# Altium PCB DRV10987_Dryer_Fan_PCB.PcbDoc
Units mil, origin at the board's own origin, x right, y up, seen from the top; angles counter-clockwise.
Board outline 2502.18 x 2296.58 mil, 2 copper layers (Top Layer, Bottom Layer), stack 65.2 mil thick; 22 components, 16 nets, 63 pads, 534 vias.
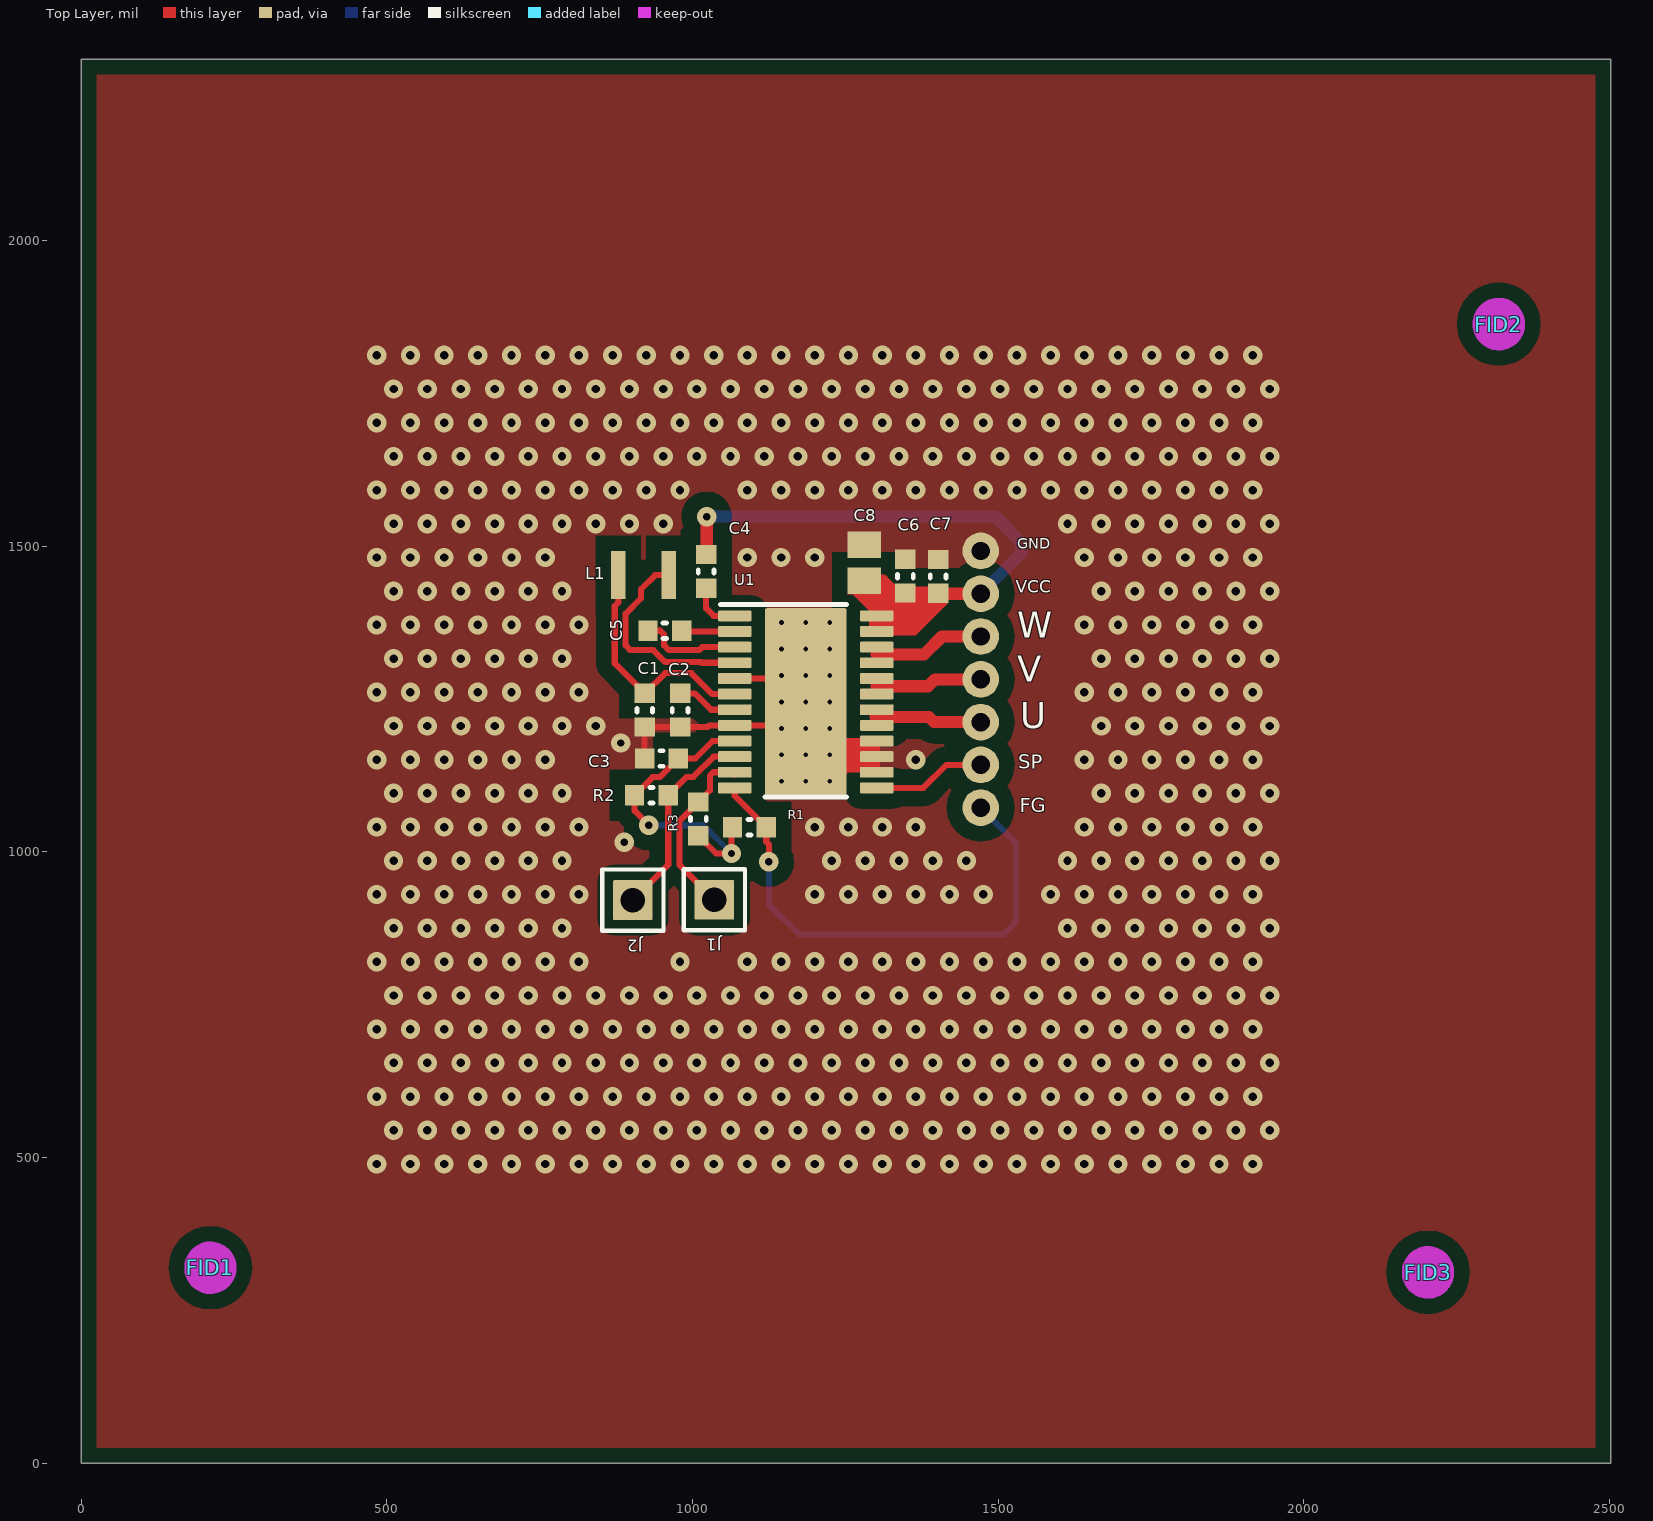
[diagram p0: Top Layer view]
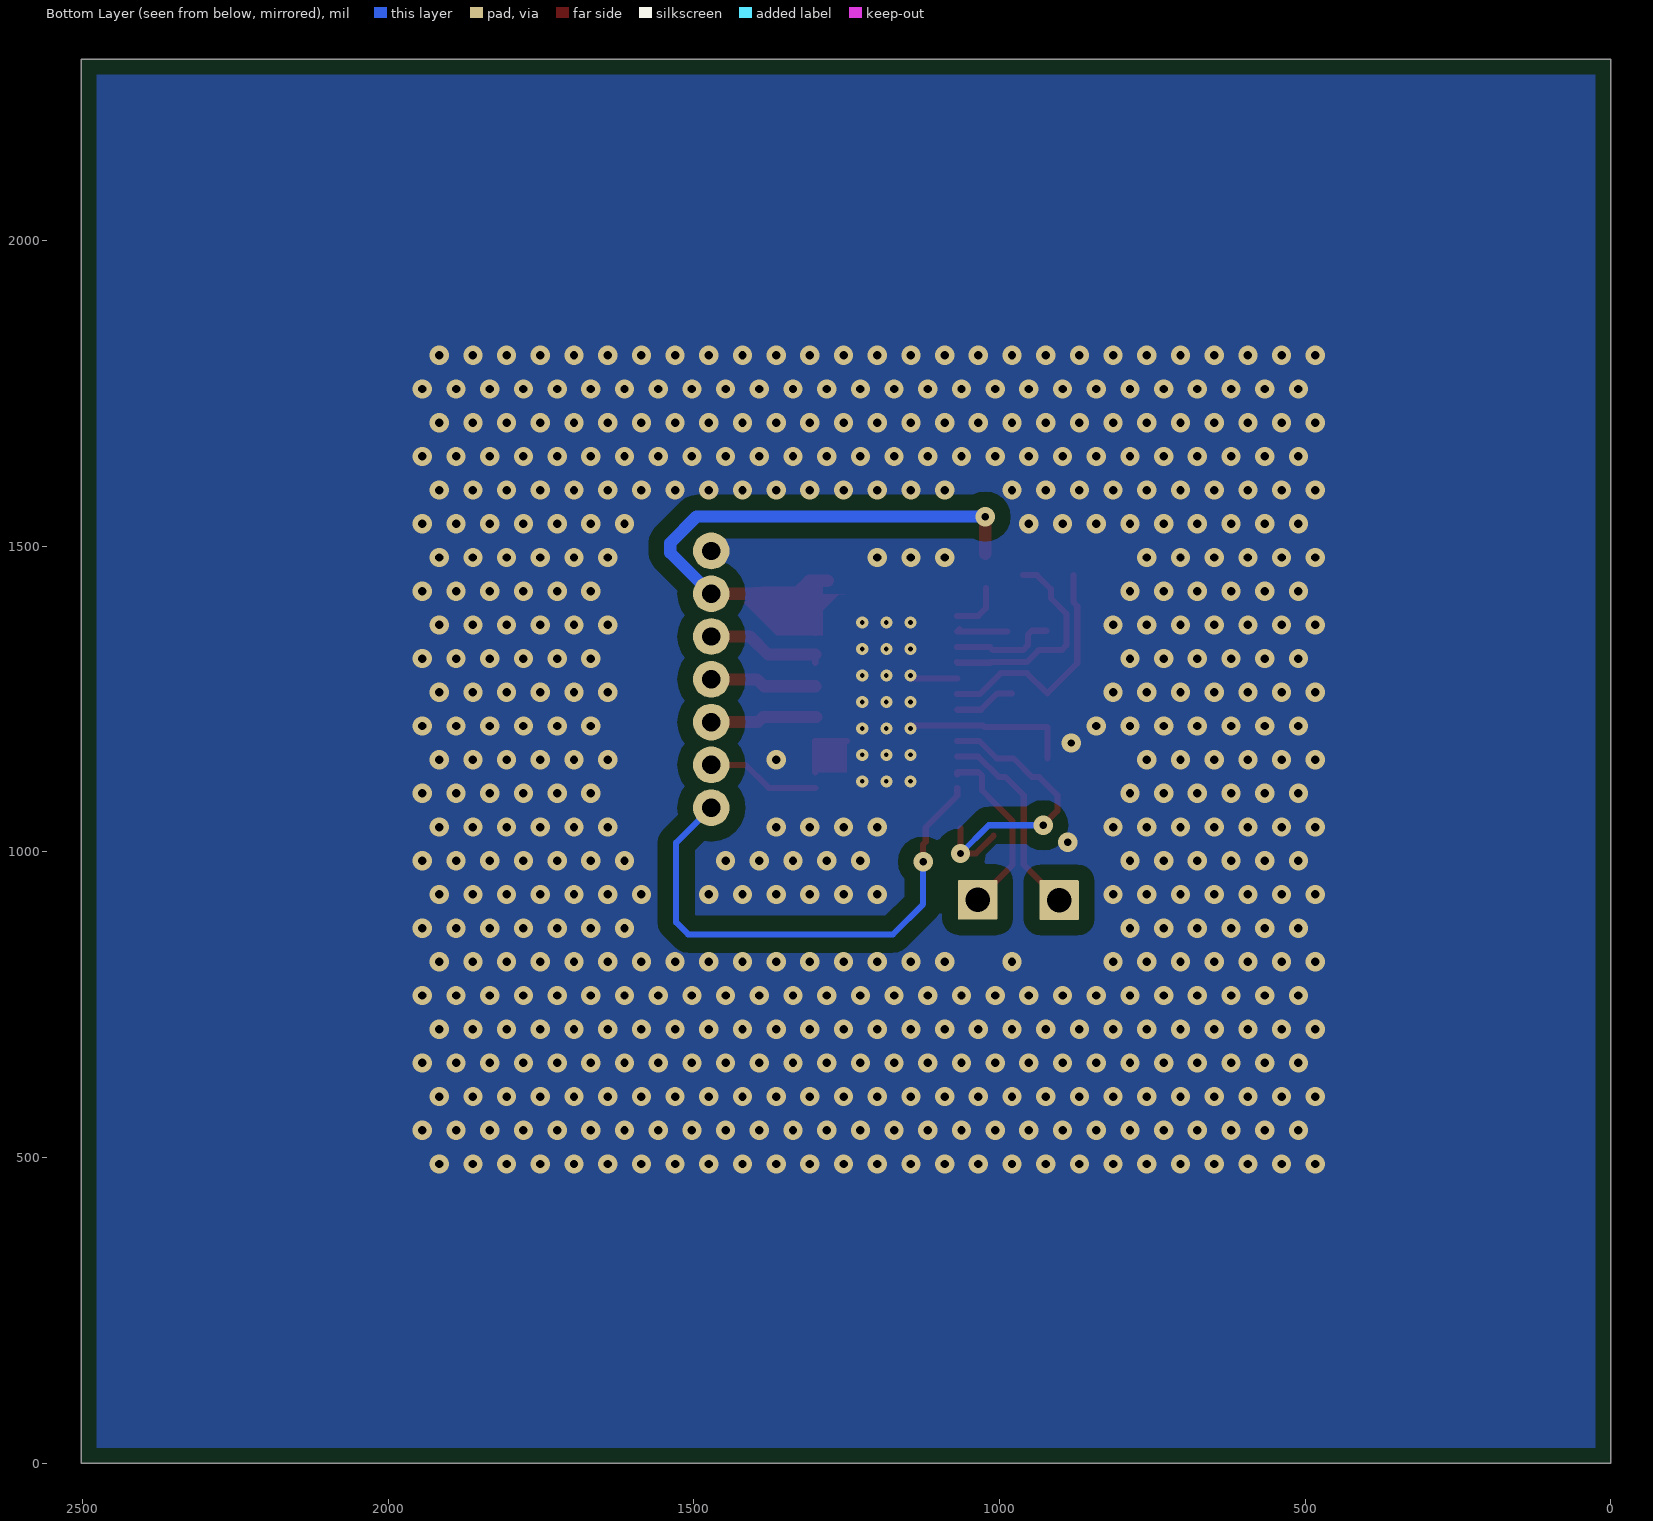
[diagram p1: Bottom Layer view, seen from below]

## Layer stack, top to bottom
Top Solder: solder mask 0.4, Solder Resist, Dk 3.5
Top Layer: signal copper 3
Dielectric1: core 59.2, FR-4, Dk 4.8
Bottom Layer: signal copper 3
Bottom Solder: solder mask 0.4, Solder Resist, Dk 3.5

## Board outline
0,0 0,2296.58 2502.18,2296.58 2502.18,0

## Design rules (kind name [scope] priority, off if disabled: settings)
AcuteAngle [All] p1: minimum=4.50000000000000E+0001 checktracksonly=FALSE
AssemblyTestPointUsage [All] p1: valid=2
BoardOutlineClearance BoardOutlineClearance_MountingHoles [OnCopper and InComponentClass('Mounting Holes')] p1: gap=40 ignorepadtopadclearanceinfootprint=FALSE
BoardOutlineClearance BoardOutlineClearance_Poly [OnCopper and IsPoly] p2: gap=25 ignorepadtopadclearanceinfootprint=FALSE
BoardOutlineClearance [OnCopper and Not InComponentClass('Logo') and not InComponentClass('FiducialMark') and not InRegion(1000,500,4000,800) and not InPoly] p3: gap=75 ignorepadtopadclearanceinfootprint=FALSE
Clearance "Stitching GND" [IsStitchingVia and InNet('GND') vs (IsVia and (Not IsStitchingVia)) Or IsPad] p1: gap=5 ignorepadtopadclearanceinfootprint=FALSE except(0: Arc-Hole Track-Hole SMDPad-Hole THPad-Hole Via-Hole Fill-Hole Poly-Hole Region-Hole Text-Hole)
Clearance Clearance_Keepouts [((IsTrack Or IsArc) And Not InPoly) And IsFree and IsKeepOut vs ((IsTrack Or IsArc) And Not InPoly) And IsFree and IsKeepOut] p2: gap=0 ignorepadtopadclearanceinfootprint=FALSE
Clearance Clearance_FiducialMark [IsKeepOut and InComponentClass('FiducialMark') vs IsPad and InComponentClass('FiducialMark')] p3: gap=0 ignorepadtopadclearanceinfootprint=FALSE
Clearance Clearance_Poly [InPolygon] p4: gap=25 ignorepadtopadclearanceinfootprint=FALSE except(0: Arc-Hole Track-Hole SMDPad-Hole THPad-Hole Via-Hole Fill-Hole Poly-Hole Region-Hole Text-Hole)
Clearance [All] p5: gap=7.87 ignorepadtopadclearanceinfootprint=FALSE except(0: Arc-Hole Track-Hole SMDPad-Hole THPad-Hole Via-Hole Fill-Hole Poly-Hole Region-Hole Text-Hole)
ComponentClearance ComponentClearance_MountingHoles_FiducialMarks [InComponentClass('Mounting Holes') vs InComponentClass('FiducialMark')] p1: gap=50 collisioncheckmode=3 verticalgap=10 showdistances=FALSE
ComponentClearance ComponentClearance_Shunt [InComponentClass('Header') vs InComponentClass('Shunt')] p2: gap=0 collisioncheckmode=3 verticalgap=0 showdistances=FALSE
ComponentClearance ComponentClearance_Logo [InComponentClass('Logo')] p3: gap=50 collisioncheckmode=3 verticalgap=10 showdistances=FALSE
ComponentClearance ComponentClearance_ScrewToNut [(HasFootprint('NY PMS 440 0025 PH')) vs (HasFootprint('Keystone_1902C'))] p4: gap=5 collisioncheckmode=3 verticalgap=10 showdistances=FALSE
ComponentClearance ComponentClearance_MountingHoles [InComponentClass('Mounting Holes')] p5: gap=250 collisioncheckmode=3 verticalgap=100000 showdistances=FALSE
ComponentClearance ComponentClearance_SmallPassives [HasFootprint('0201*') or HasFootprint('0402*') or HasFootprint('0508') or HasFootprint('0603*') or HasFootprint('0612') or HasFootprint('0805*') or HasFootprint('0815*') or HasFootprint('0830*') or HasFootprint('1206*') or HasFootprint('1210*') or HasFootprint('1808*') or HasFootprint('1812*') or HasFootprint('1825*') or HasFootprint('2010*') or HasFootprint('2220*') or HasFootprint('2225*') or HasFootprint('2512*') or HasFootprint('2728*') or HasFootprint('3518*') vs HasFootprint('0201*') or HasFootprint('0402*') or HasFootprint('0508') or HasFootprint('0603*') or HasFootprint('0612') or HasFootprint('0805*') or HasFootprint('0815*') or HasFootprint('0830*') or HasFootprint('1206*') or HasFootprint('1210*') or HasFootprint('1808*') or HasFootprint('1812*') or HasFootprint('1825*') or HasFootprint('2010*') or HasFootprint('2220*') or HasFootprint('2225*') or HasFootprint('2512*') or HasFootprint('2728*') or HasFootprint('3518*')] p6: gap=14.96 collisioncheckmode=3 verticalgap=10 showdistances=FALSE
ComponentClearance ComponentClearance_THtoSMT [IsThruComponent vs IsSMTComponent] p7: gap=40 collisioncheckmode=3 verticalgap=30 showdistances=FALSE
ComponentClearance ComponentClearance_THtoTH [IsThruComponent vs IsThruComponent] p8: gap=30 collisioncheckmode=3 verticalgap=30 showdistances=FALSE
ComponentClearance [All] p9: gap=30 collisioncheckmode=3 verticalgap=10 showdistances=FALSE
DiffPairsRouting [All] p1: maxlimit=100 minlimit=10 mostfreqgap=10 toplayer_minwidth=15 toplayer_maxwidth=15 toplayer_prefwidth=15 bottomlayer_minwidth=15 bottomlayer_maxwidth=15 bottomlayer_prefwidth=15 maxuncoupledlength=1000
FabricationTestPointUsage TestPointUsage [All] p1: valid=2 allowmultiple=FALSE
FabricationTestpoint Testpoint [All] p1: side=3 testpointundercomponent=TRUE minsize=40 maxsize=100 preferedsize=60 minholesize=0 maxholesize=40 preferedholesize=32 testpointgrid=1 allowsidetop=TRUE allowsidebottom=TRUE usegrid=TRUE gridtolerance=0.01
FanoutControl Fanout_LCC [IsLCC] p1: bgadir=Out bgaviamode=Centered fanoutstyle=Auto fanoutdirection=Alternating viagrid=1 // Fanout_LCC (Default Rule)
FanoutControl Fanout_BGA [IsBGA] p2: bgadir=Out bgaviamode=Centered fanoutstyle=Auto fanoutdirection=Alternating viagrid=1 // Fanout_BGA (Default Rule)
FanoutControl Fanout_Default [All] p4: bgadir=Out bgaviamode=Centered fanoutstyle=Auto fanoutdirection=Alternating viagrid=1 // Fanout_Default (Default Rule)
FanoutControl Fanout_Small [(CompPinCount < 5)] p5: bgadir=Out bgaviamode=Centered fanoutstyle=Auto fanoutdirection=OutThenIn viagrid=1 // Fanout_Small (Default Rule)
HoleSize [All] p1: absolutevalues=TRUE maxlimit=251 minlimit=7.87 maxpercent=80.000 minpercent=20.000
MinimumAnnularRing MinimumAnnularRing_ThermalPadVias [IsVia and InAnyComponent] p1: minimumring=5.91
MinimumAnnularRing [All] p2: minimumring=8
MinimumSolderMaskSliver MinimumSolderMaskSliver_Logo [InComponentClass('Logo') vs InComponentClass('Logo')] p1: minsoldermaskwidth=0.7
MinimumSolderMaskSliver [All] p2: minsoldermaskwidth=3.94
PlaneConnect [All] p1: planeconnectstyle=Relief reliefexpansion=10 reliefentries=4 reliefconductorwidth=10 reliefairgap=10
PolygonConnect PolygonConnect_1 [All vs IsNamedPolygon('Top Layer-No Net')] p1: connectstyle=Direct reliefconductorwidth=10 reliefentries=4 polygonreliefangle="90 Angle" airgapwidth=10
PolygonConnect [All] p2: connectstyle=Relief reliefconductorwidth=10 reliefentries=4 polygonreliefangle="90 Angle" airgapwidth=10
RoutingVias ThermalPadVias [IsVia and InAnyComponent] p1: holewidth=7.87 width=19.68 viastyle="Through Hole" minholewidth=7.87 minwidth=19.68 maxholewidth=12.99 maxwidth=23.62
RoutingVias [All] p2: holewidth=16 width=34 viastyle="Through Hole" minholewidth=7.87 minwidth=26 maxholewidth=40 maxwidth=65
SilkToBoardRegionClearance [Not ((IsComment or IsDesignator) And (Hide <> 'False')) and not InRegion(1000,500,4000,800)] p1:
SilkToSilkClearance SilkToSilkClearance_Pb-FreeLogo [(HasFootprint('Pb-Free_Overlay_Medium') OR HasFootprint('Pb-Free_Overlay_Small')) vs (HasFootprint('Pb-Free_Overlay_Medium') OR HasFootprint('Pb-Free_Overlay_Small'))] p1: silktosilkclearance=0
SilkToSilkClearance [All] p2: silktosilkclearance=4
SilkToSolderMaskClearance SilkToComponentPadClearance [(IsPad or IsFill or IsRegion) and InAnycomponent] p1: minsilkscreentomaskgap=5 clearancetoexposedcopper=TRUE
SilkToSolderMaskClearance "Silk to Solder Mask Opening" [All] p2: minsilkscreentomaskgap=4 clearancetoexposedcopper=FALSE
SolderMaskExpansion [All] p1: expansion=1.97
Width [All] p1: maxlimit=100 minlimit=6 preferedwidth=10 checkconnectedcopper=TRUE
15 further rules are at their usual default settings.

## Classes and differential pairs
component class Header: J1 J2
component class DRV10987_Dryer_Fan_BlankSheet: C1 C2 C3 C4 C5 C6 C7 C8 J1 J2 L1 R1 R2 R3 U1
component class DRV10987_Dryer_Fan_EVM_Hardware: FID1 FID2 FID3 ZZ1 ZZ2 ZZ3 ZZ4
component class FiducialMark: FID1 FID2 FID3
component class AssemblyNote: ZZ1 ZZ2 ZZ3 ZZ4

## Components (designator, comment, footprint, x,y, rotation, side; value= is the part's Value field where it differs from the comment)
C1 "C1608X6S1A106M080AC" 0603L 921.77,1231.62 r270 top value=10uF
C2 "GRM185C80J105KE26D" 0603L 979.72,1231.65 r270 top value=1uF
C3 "GRM185C80J105KE26D" 0603L 949.25,1152.65 r180 top value=1uF
C4 "06035C104KAT2A" 0603L 1022.33,1458.68 r90 top value=0.1uF
C5 "0603ZC103KAT2A" 0603L 954.7,1361.58 r0 top value=0.01uF
C6 "GRM188R6YA106MA73" 0603L 1401.73,1450.45 r90 top value=10uF
C7 "C0603C101J5GAC" 0603L 1348.21,1450.82 r270 top value=100pF
C8 "GRM21BR6YA106KE43L" 0805L 1280.8,1472.75 r90 top value=10uF
FID1 "Fiducial" Fiducial6.4-20 211.44,319.55 r0 top
FID2 "Fiducial" Fiducial6.4-20 2318.85,1863.24 r0 top
FID3 "Fiducial" Fiducial6.4-20 2203.12,312.08 r0 top
J1 "TSW-101-07-G-S" TSW-101-07-G-S 1035.71,921.55 r0 top
J2 "TSW-101-07-G-S" TSW-101-07-G-S 902.46,921.09 r0 top
L1 "CB2518T470K" IND_CB2518 920.06,1452.62 r180 top value=47uH
R1 "CRCW06034K75FKEA" 0603L 1093.03,1040.14 r0 top value=4.75k
R2 "CRCW06034K75FKEA" 0603L 932.72,1092.6 r0 top value=4.75k
R3 "CRCW06034K75FKEA" 0603L 1009.69,1053.8 r90 top value=4.75k
U1 "DRV10987PWPR" PWP0024B_N 1185.16,1245.24 r0 top
ZZ1 "This Assembly Note is for PCB labels only" AssemblyNoteLabel 185,3938 r0 top
ZZ2 "These assemblies are ESD sensitive, ESD precautions shall be observed." AssemblyNote 185,3829.11 r0 top
ZZ3 "These assemblies must be clean and free from flux and all contaminants. Use of no clean flux is not acceptable." AssemblyNote 185,3740.56 r0 top
ZZ4 "These assemblies must comply with workmanship standards IPC-A-610 Class 2, unless otherwise specified." AssemblyNote 185,3652 r0 top

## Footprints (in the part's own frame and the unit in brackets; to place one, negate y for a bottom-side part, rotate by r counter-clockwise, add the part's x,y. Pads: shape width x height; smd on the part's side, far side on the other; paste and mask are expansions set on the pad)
0603L [mm] "0603 from SM-752 data"
  rect 0.8x0.85 smd: 1(-0.7,0) 2(0.7,0)
  silkscreen extent -0.07,-0.33 0.07,0.33, body extent -0.87,-0.47 0.87,0.47, height 1
0805L [mm] "0805 from SM-752 data"
  rect 1.1x1.4 smd: 1(-0.75,0) 2(0.75,0)
  body extent -1.1,-0.72 1.1,0.72, height 1.45
AssemblyNote [mil] "Assembly Note"
AssemblyNoteLabel [mil] "Assembly Note for PCB Labels"
Fiducial6.4-20 [mil]
  round 25 smd mask+26.87: 1(0,0)
  Top Layer keep-out circle w46.37: c0,0 r19.68
IND_CB2518 [mm] "TAIYO YUDEN"
  rect 0.6x2 smd: 1(-1.05,0) 2(1.05,0)
  body extent -1.35,-1 1.35,1, height 2
PWP0024B_N [mm] "TSOP, 24-Leads, Body 7.9x4.5mm (max), Pitch 0.65mm, IPC Medium Density"
  rrect22% 1.4x0.45 smd: 1(-2.95,3.575) 2(-2.95,2.925) 3(-2.95,2.275) 4(-2.95,1.625) 5(-2.95,0.975) 6(-2.95,0.325) 7(-2.95,-0.325) 8(-2.95,-0.975) 9(-2.95,-1.625) 10(-2.95,-2.275) 11(-2.95,-2.925) 12(-2.95,-3.575) 13(2.95,-3.575) 14(2.95,-2.925) 15(2.95,-2.275) 16(2.95,-1.625) 17(2.95,-0.975) 18(2.95,-0.325) 19(2.95,0.325) 20(2.95,0.975) 21(2.95,1.625) 22(2.95,2.275) 23(2.95,2.925) 24(2.95,3.575)
  rrect6% 3.4x7.8 smd paste-2 mask-2: 25(0,0)
  rrect4% 2.4x5.16 on Top Paste: 25(0,0)
  rrect4% 2.4x5.16 on Top Solder: 25(0,0)
  silkscreen extent -3.55,-3.95 1.7,4.05, body extent -3.21,-3.9 3.21,3.9, height 1.2
TSW-101-07-G-S [mm] "Samtec 100mil, 1pos, 230 mil above insulator"
  rrect6% 1.65x1.65 hole 1.016: 1(0,0)
  silkscreen extent -1.27,-1.27 1.27,1.27, body extent -1.27,-1.27 1.27,1.27, height 8.38

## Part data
C1: "CAP, CERM, 10 µF, 10 V, +/- 10%, X6S, 0603", Cap_Case=0603, Manufacturer=TDK, Supplier Part Number 1=445-9019-1-ND, TempCo=X6S, Tolerance_%=10, Value1="0.004639 ohm", Value2=10V, ValueDisplayed=10µF
C2 C3: "CAP, CERM, 1 µF, 6.3 V, +/- 10%, X6S, 0603", Cap_Case=0603, Manufacturer=MuRata, Supplier Part Number 1=GRM185C80J105KE26D-ND, TempCo=X6S, Tolerance_%=10, Value1=Unknown, Value2=6.3V, ValueDisplayed=1µF
C4: "CAP, CERM, 0.1uF, 50V, +/-10%, X7R, 0603", Cap_Case=0603, Manufacturer=AVX, Supplier Part Number 1=478-5052-1-ND, TempCo=X7R, Tolerance_%=10, Value1=Unknown, Value2=50V, ValueDisplayed=0.1µF
C5: "CAP, CERM, 0.01 µF, 10 V, +/- 10%, X7R, 0603", Cap_Case=0603, Manufacturer=AVX, Supplier Part Number 1=478-7938-2-ND, TempCo=X7R, Tolerance_%=10, Value1=Unknown, Value2=10V, ValueDisplayed=0.01µF
C6: "CAP, CERM, 10 µF, 35 V, +/- 20%, X5R, 0603", Cap_Case=0603, Manufacturer=Nichicon, TempCo=X5R, Tolerance_%=20, Value1=Unknown, Value2=35V, ValueDisplayed=10µF
C7: "CAP, CERM, 100 pF, 50 V, +/- 5%, C0G/NP0, 0603", Cap_Case=0603, Manufacturer=Kemet, Supplier Part Number 1=1414602, TempCo=C0G/NP0, Tolerance_%=5, Value1=Unknown, Value2=50V, ValueDisplayed=100pF
C8: "CAP, CERM, 10 µF, 35 V, +/- 10%, X5R, 0805", Cap_Case=0805, Manufacturer=MuRata, Supplier Part Number 1=490-10514-1-ND, TempCo=X5R, Tolerance_%=10, Value1=Unknown, Value2=35V, ValueDisplayed=10µF
FID1 FID2 FID3: "Fiducial mark.  There is nothing to buy or mount.", Manufacturer=N/A
J1 J2: "Header, 100mil, 1pos, Gold, TH", Color=Black, Current_A=6.3, Manufacturer=Samtec, Supplier Part Number 1=SAM1029-01-ND, Voltage_V=550
L1: "Inductor, Wirewound, Ferrite, 47 µH, 0.11 A, 1.235 ohm, SMD", Manufacturer="Taiyo Yuden", Supplier Part Number 1=587-2191-1-ND, Value1="1.235 ohm", Value2=0.11A, ValueDisplayed=47µH
R1 R2 R3: "RES, 4.75k ohm, 1%, 0.1W, 0603", Manufacturer=Vishay-Dale, Power_W=0.1, Supplier Part Number 1=541-4.75KHCT-ND, TempCo="100 ppm/C", Tolerance_%=1, Value1=1%, Value2=0.1W, Value_Code=4k75
U1: "12- to 24-V, Three-Phase, Sensorless BLDC Motor Driver, PWP0024B (TSSOP-24)", Alternate Manufacturer="Texas Instruments", Alternate PartNumber=DRV10987PWP
ZZ1: library part AssemblyNoteLabel, Alternate Manufacturer=-
ZZ2 ZZ3 ZZ4: library part AssemblyNote, Alternate Manufacturer=-

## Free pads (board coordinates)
  round 60 hole 30: 2(1471.46,1422.16) 4(1471.46,1212.16) 5(1471.46,1142.16) 6(1471.46,1072.16) 7(1471.46,1492.16) 8(1471.46,1352.16) 9(1471.46,1282.16)

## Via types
v1: diameter 31.5, hole 13.78, Top Layer to Bottom Layer, 507 vias
v2: diameter 19.68, hole 7.87, Top Layer to Bottom Layer, 15 vias
v3: diameter 31.5, hole 11.81, Top Layer to Bottom Layer, 6 vias
v4: diameter 19.68, hole 7.87, Top Layer to Bottom Layer, tented both sides, 6 vias

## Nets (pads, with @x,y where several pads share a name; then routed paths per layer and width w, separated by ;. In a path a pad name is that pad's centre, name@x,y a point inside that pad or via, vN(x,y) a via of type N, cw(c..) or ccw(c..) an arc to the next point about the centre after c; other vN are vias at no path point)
FG: pad.6 R1.2 U1.12 | length 857.3
  Top Layer w10: U1.12 1069.02,1091.7 R1.2 1120.59,1016.4 1124.82,1012.17 v3(1124.82,983.76)
  Bottom Layer w10: v3(1124.82,983.76) 1124.82,914.33 1174.21,864.93 1509.12,864.93 1528.9,884.71 1528.9,1014.72 pad.6
GND: C1.2 C2.2 C3.2 C6.2 C7.1 C8.2 pad.7 U1.5 U1.8 U1.14 U1.15 U1.16 U1.25@1185.16,1245.24 | length 458.6
  Top Layer w10: C3.2@921.77,1152.73 C1.2 ; C1.2 C2.2 C2.2 1024.62,1204.06 1027.41,1206.85 U1.8 U1.25@1146.78,1206.85 ; U1.5 U1.25@1146.78,1283.62 ; U1.25@1249.14,1181.26 U1.16 U1.15 U1.14
  other v1: 483.44,489.3 538.56,489.3 593.68,489.3 648.8,489.3 703.91,489.3 759.03,489.3 814.15,489.3 869.27,489.3 924.39,489.3 979.5,489.3 1034.62,489.3 1089.74,489.3 1144.86,489.3 1199.98,489.3 1255.1,489.3 1310.21,489.3 1365.33,489.3 1420.45,489.3 1475.57,489.3 1530.69,489.3 1585.8,489.3 1640.92,489.3 1696.04,489.3 1751.16,489.3 1806.28,489.3 1861.39,489.3 1916.51,489.3 511,544.42 566.12,544.42 621.24,544.42 676.36,544.42 731.47,544.42 786.59,544.42 841.71,544.42 896.83,544.42 951.95,544.42 1007.06,544.42 1062.18,544.42 1117.3,544.42 1172.42,544.42 1227.54,544.42 1282.65,544.42 1337.77,544.42 1392.89,544.42 1448.01,544.42 1503.13,544.42 1558.24,544.42 1613.36,544.42 1668.48,544.42 1723.6,544.42 1778.72,544.42 1833.84,544.42 1888.95,544.42 1944.07,544.42 483.44,599.54 538.56,599.54 593.68,599.54 648.8,599.54 703.91,599.54 759.03,599.54 814.15,599.54 869.27,599.54 924.39,599.54 979.5,599.54 1034.62,599.54 1089.74,599.54 1144.86,599.54 1199.98,599.54 1255.1,599.54 1310.21,599.54 1365.33,599.54 1420.45,599.54 1475.57,599.54 1530.69,599.54 1585.8,599.54 1640.92,599.54 1696.04,599.54 1751.16,599.54 1806.28,599.54 1861.39,599.54 1916.51,599.54 511,654.66 566.12,654.66 621.24,654.66 676.36,654.66 731.47,654.66 786.59,654.66 841.71,654.66 896.83,654.66 951.95,654.66 1007.06,654.66 1062.18,654.66 1117.3,654.66 1172.42,654.66 1227.54,654.66 1282.65,654.66 1337.77,654.66 1392.89,654.66 1448.01,654.66 1503.13,654.66 1558.24,654.66 1613.36,654.66 1668.48,654.66 1723.6,654.66 1778.72,654.66 1833.84,654.66 1888.95,654.66 1944.07,654.66 483.44,709.78 538.56,709.78 593.68,709.78 648.8,709.78 703.91,709.78 759.03,709.78 814.15,709.78 869.27,709.78 924.39,709.78 979.5,709.78 1034.62,709.78 1089.74,709.78 1144.86,709.78 1199.98,709.78 1255.1,709.78 1310.21,709.78 1365.33,709.78 1420.45,709.78 1475.57,709.78 1530.69,709.78 1585.8,709.78 1640.92,709.78 1696.04,709.78 1751.16,709.78 1806.28,709.78 1861.39,709.78 1916.51,709.78 511,764.89 566.12,764.89 621.24,764.89 676.36,764.89 731.47,764.89 786.59,764.89 841.71,764.89 896.83,764.89 951.95,764.89 1007.06,764.89 1062.18,764.89 1117.3,764.89 1172.42,764.89 1227.54,764.89 1282.65,764.89 1337.77,764.89 1392.89,764.89 1448.01,764.89 1503.13,764.89 1558.24,764.89 1613.36,764.89 1668.48,764.89 1723.6,764.89 1778.72,764.89 1833.84,764.89 1888.95,764.89 1944.07,764.89 483.44,820.01 538.56,820.01 593.68,820.01 648.8,820.01 703.91,820.01 759.03,820.01 814.15,820.01 979.5,820.01 1089.74,820.01 1144.86,820.01 1199.98,820.01 1255.1,820.01 1310.21,820.01 1365.33,820.01 1420.45,820.01 1475.57,820.01 1530.69,820.01 1585.8,820.01 1640.92,820.01 1696.04,820.01 1751.16,820.01 1806.28,820.01 1861.39,820.01 1916.51,820.01 511,875.13 566.12,875.13 621.24,875.13 676.36,875.13 731.47,875.13 786.59,875.13 1613.36,875.13 1668.48,875.13 1723.6,875.13 1778.72,875.13 1833.84,875.13 1888.95,875.13 1944.07,875.13 483.44,930.25 538.56,930.25 593.68,930.25 648.8,930.25 703.91,930.25 759.03,930.25 814.15,930.25 1199.98,930.25 1255.1,930.25 1310.21,930.25 1365.33,930.25 1420.45,930.25 1475.57,930.25 1585.8,930.25 1640.92,930.25 1696.04,930.25 1751.16,930.25 1806.28,930.25 1861.39,930.25 1916.51,930.25 511,985.37 566.12,985.37 621.24,985.37 676.36,985.37 731.47,985.37 786.59,985.37 1227.54,985.37 1282.65,985.37 1337.77,985.37 1392.89,985.37 1448.01,985.37 1613.36,985.37 1668.48,985.37 1723.6,985.37 1778.72,985.37 1833.84,985.37 1888.95,985.37 1944.07,985.37 483.44,1040.49 538.56,1040.49 593.68,1040.49 648.8,1040.49 703.91,1040.49 759.03,1040.49 814.15,1040.49 1199.98,1040.49 1255.1,1040.49 1310.21,1040.49 1365.33,1040.49 1640.92,1040.49 1696.04,1040.49 1751.16,1040.49 1806.28,1040.49 1861.39,1040.49 1916.51,1040.49 511,1095.6 566.12,1095.6 621.24,1095.6 676.36,1095.6 731.47,1095.6 786.59,1095.6 1668.48,1095.6 1723.6,1095.6 1778.72,1095.6 1833.84,1095.6 1888.95,1095.6 1944.07,1095.6 483.44,1150.72 538.56,1150.72 593.68,1150.72 648.8,1150.72 703.91,1150.72 759.03,1150.72 1365.33,1150.72 1640.92,1150.72 1696.04,1150.72 1751.16,1150.72 1806.28,1150.72 1861.39,1150.72 1916.51,1150.72 511,1205.84 566.12,1205.84 621.24,1205.84 676.36,1205.84 731.47,1205.84 786.59,1205.84 841.71,1205.84 1668.48,1205.84 1723.6,1205.84 1778.72,1205.84 1833.84,1205.84 1888.95,1205.84 1944.07,1205.84 483.44,1260.96 538.56,1260.96 593.68,1260.96 648.8,1260.96 703.91,1260.96 759.03,1260.96 814.15,1260.96 1640.92,1260.96 1696.04,1260.96 1751.16,1260.96 1806.28,1260.96 1861.39,1260.96 1916.51,1260.96 511,1316.08 566.12,1316.08 621.24,1316.08 676.36,1316.08 731.47,1316.08 786.59,1316.08 1668.48,1316.08 1723.6,1316.08 1778.72,1316.08 1833.84,1316.08 1888.95,1316.08 1944.07,1316.08 483.44,1371.19 538.56,1371.19 593.68,1371.19 648.8,1371.19 703.91,1371.19 759.03,1371.19 814.15,1371.19 1640.92,1371.19 1696.04,1371.19 1751.16,1371.19 1806.28,1371.19 1861.39,1371.19 1916.51,1371.19 511,1426.31 566.12,1426.31 621.24,1426.31 676.36,1426.31 731.47,1426.31 786.59,1426.31 1668.48,1426.31 1723.6,1426.31 1778.72,1426.31 1833.84,1426.31 1888.95,1426.31 1944.07,1426.31 483.44,1481.43 538.56,1481.43 593.68,1481.43 648.8,1481.43 703.91,1481.43 759.03,1481.43 1089.74,1481.43 1144.86,1481.43 1199.98,1481.43 1640.92,1481.43 1696.04,1481.43 1751.16,1481.43 1806.28,1481.43 1861.39,1481.43 1916.51,1481.43 511,1536.55 566.12,1536.55 621.24,1536.55 676.36,1536.55 731.47,1536.55 786.59,1536.55 841.71,1536.55 896.83,1536.55 951.95,1536.55 1613.36,1536.55 1668.48,1536.55 1723.6,1536.55 1778.72,1536.55 1833.84,1536.55 1888.95,1536.55 1944.07,1536.55 483.44,1591.67 538.56,1591.67 593.68,1591.67 648.8,1591.67 703.91,1591.67 759.03,1591.67 814.15,1591.67 869.27,1591.67 924.39,1591.67 979.5,1591.67 1089.74,1591.67 1144.86,1591.67 1199.98,1591.67 1255.1,1591.67 1310.21,1591.67 1365.33,1591.67 1420.45,1591.67 1475.57,1591.67 1530.69,1591.67 1585.8,1591.67 1640.92,1591.67 1696.04,1591.67 1751.16,1591.67 1806.28,1591.67 1861.39,1591.67 1916.51,1591.67 511,1646.78 566.12,1646.78 621.24,1646.78 676.36,1646.78 731.47,1646.78 786.59,1646.78 841.71,1646.78 896.83,1646.78 951.95,1646.78 1007.06,1646.78 1062.18,1646.78 1117.3,1646.78 1172.42,1646.78 1227.54,1646.78 1282.65,1646.78 1337.77,1646.78 1392.89,1646.78 1448.01,1646.78 1503.13,1646.78 1558.24,1646.78 1613.36,1646.78 1668.48,1646.78 1723.6,1646.78 1778.72,1646.78 1833.84,1646.78 1888.95,1646.78 1944.07,1646.78 483.44,1701.9 538.56,1701.9 593.68,1701.9 648.8,1701.9 703.91,1701.9 759.03,1701.9 814.15,1701.9 869.27,1701.9 924.39,1701.9 979.5,1701.9 1034.62,1701.9 1089.74,1701.9 1144.86,1701.9 1199.98,1701.9 1255.1,1701.9 1310.21,1701.9 1365.33,1701.9 1420.45,1701.9 1475.57,1701.9 1530.69,1701.9 1585.8,1701.9 1640.92,1701.9 1696.04,1701.9 1751.16,1701.9 1806.28,1701.9 1861.39,1701.9 1916.51,1701.9 511,1757.02 566.12,1757.02 621.24,1757.02 676.36,1757.02 731.47,1757.02 786.59,1757.02 841.71,1757.02 896.83,1757.02 951.95,1757.02 1007.06,1757.02 1062.18,1757.02 1117.3,1757.02 1172.42,1757.02 1227.54,1757.02 1282.65,1757.02 1337.77,1757.02 1392.89,1757.02 1448.01,1757.02 1503.13,1757.02 1558.24,1757.02 1613.36,1757.02 1668.48,1757.02 1723.6,1757.02 1778.72,1757.02 1833.84,1757.02 1888.95,1757.02 1944.07,1757.02 483.44,1812.14 538.56,1812.14 593.68,1812.14 648.8,1812.14 703.91,1812.14 759.03,1812.14 814.15,1812.14 869.27,1812.14 924.39,1812.14 979.5,1812.14 1034.62,1812.14 1089.74,1812.14 1144.86,1812.14 1199.98,1812.14 1255.1,1812.14 1310.21,1812.14 1365.33,1812.14 1420.45,1812.14 1475.57,1812.14 1530.69,1812.14 1585.8,1812.14 1640.92,1812.14 1696.04,1812.14 1751.16,1812.14 1806.28,1812.14 1861.39,1812.14 1916.51,1812.14
  other v2: 1145.79,1158.62 1185.16,1158.62 1224.53,1158.62 1145.79,1201.93 1185.16,1201.93 1224.53,1201.93 1145.79,1245.24 1185.16,1245.24 1224.53,1245.24 1145.79,1288.54 1185.16,1288.54 1224.53,1288.54 1145.79,1331.85 1185.16,1331.85 1224.53,1331.85
  other v3: 888.21,1015.52 882.46,1178.02
  other v4: 1145.79,1115.31 1185.16,1115.31 1224.53,1115.31 1145.79,1375.16 1185.16,1375.16 1224.53,1375.16
NetC1_1: C1.1 L1.2 U1.6 | length 391.5
  Top Layer w10: L1.2 878.72,1407.86 872.77,1401.91 872.77,1308.18 C1.1 955.05,1292.46 998.06,1292.46 1032.49,1258.03 U1.6
NetC2_1: C2.1 U1.7 | length 100.4
  Top Layer w10: C2.1 1003.57,1259.21 1030.35,1232.44 U1.7
NetC4_1: C4.1 U1.1 | length 84.6
  Top Layer w10: C4.1 1022.33,1398.29 1034.64,1385.98 U1.1
NetC5_1: C5.1 U1.3 | length 171.2
  Top Layer w10: C5.1@923.2,1361.58 947.25,1361.58 953.64,1355.19 953.64,1337.55 961.18,1330.01 1011.21,1330.01 1016.01,1334.8 U1.3
NetC5_2: C5.2 U1.2 | length 87.1
  Top Layer w10: C5.2@987.39,1360.39 U1.2 U1.2@1065.16,1364.25
NetL1_1: L1.1 U1.4 | length 348.8
  Top Layer w10: L1.1 938.87,1452.62 915.77,1429.52 915.77,1414.64 890.65,1389.52 890.65,1337.55 898.19,1330.01 935.9,1330.01 955.58,1310.33 1013.53,1310.33 1014.65,1309.21 U1.4 U1.4@1069.02,1310.33
SCL: J2.1 R2.2 U1.10 | length 330.3
  Top Layer w10: J2.1 960.28,978.91 R2.2 990.3,1122.62 1001.53,1122.62 1034.57,1155.67 U1.10
SDA: J1.1 R3.2 U1.11 | length 293.9
  Top Layer w10: J1.1 978.54,978.72 978.54,1050.21 R3.2 1028.59,1100.26 1028.59,1124.41 1034.26,1130.08 U1.11 U1.11@1069.02,1126.22
SPEED: pad.5 U1.13 | length 185.8
  Top Layer w10: U1.13 1377.82,1104.49 1415.5,1142.16 pad.5
U: pad.4 U1.17 U1.18 | length 175.4
  Top Layer w19.68: 1299.43,1220.23 1387.14,1220.23 1395.2,1212.16 pad.4
V: pad.9 U1.19 U1.20 | length 174.9
  Top Layer w19.68: 1301.31,1270.83 1385.29,1270.83 1396.63,1282.16 pad.9
V3P3: C3.1 R1.1 R2.1 R3.1 U1.9 | length 521.2
  Top Layer w10: v3(928.53,1043.42) 905.16,1066.79 R2.1 934.77,1122.2 946.36,1122.2 C3.1 1004.55,1152.65 1033.16,1181.26 U1.9 ; R3.1 1038.69,997.24 v3(1063.79,997.24) R1.1@1063.79,1038.46
  Bottom Layer w10: v3(928.53,1043.42) 1017.61,1043.42 v3(1063.79,997.24)
VCC: C4.2 C6.1 C7.2 C8.1 pad.2 U1.23 U1.24 | length 925.3
  Top Layer w15.75: C6.1@1401.37,1423.26 C6.1 C6.1@1402.46,1422.16
  Top Layer w20: C4.2@1023.2,1487.1 v3(1023.2,1548.26) ; C8.1 1311.36,1443.22 1331.32,1423.26 C7.2 C6.1@1401.37,1423.26 ; C6.1@1402.46,1422.16 pad.2
  Top Layer w25: U1.23@1301.31,1365.31 U1.24
  Bottom Layer w20: v3@1023.33,1548.39 1495.48,1548.39 1538.66,1505.21 1538.66,1489.36 pad.2
W: pad.8 U1.21 U1.22 | length 196.1
  Top Layer w10: U1.21 1301.31,1323.1
  Top Layer w19.68: 1301.31,1323.1 1379.04,1323.1 1408.11,1352.16 pad.8
pads on no net: FID1.1 FID2.1 FID3.1 U1.25@1185.16,1245.24

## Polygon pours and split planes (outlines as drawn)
GND on Top Layer "Top Layer-No Net" (solid, pour order 9): 0,0 0,2296.58 2502.18,2296.58 2502.18,0
GND on Bottom Layer "Top Layer-No Net" (solid, pour order 16): 0,0 0,2296.58 2502.18,2296.58 2502.18,0

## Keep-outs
Keep-Out Layer:
  text ".Layer_Name" at 577,-858.49 h60

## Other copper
Top Layer:
  rectangle net GND: 1249.14,1130.08 1301.31,1181.26
  region net VCC: 1253.22,1421.66 1261.76,1421.66 1289.17,1394.25 1289.67,1394.76 1289.67,1422.15
  region net VCC: 1418.43,1407.42 1365.25,1354.24 1290.88,1354.24 1290.19,1353.56 1289.17,1354.59 1289.17,1433.92 1390.7,1433.92 1401.37,1423.26
  text ".Layer_Name" at 577,-858.49 h60
Bottom Layer:
  text ".Layer_Name" at 577,-858.49 h60

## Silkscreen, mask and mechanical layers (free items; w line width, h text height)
Top Overlay:
  text "GND" at 1530.9,1489.61 h30
  text "VCC" at 1528.42,1416.52 h35
  text "W" at 1531.13,1335.84 h72.83
  text "V" at 1531.13,1263.88 h72.83
  text "U" at 1535.99,1188.02 h72.83
  text "SP" at 1533.08,1127.73 h40
  text "FG" at 1535.02,1056.74 h40
  text ".Layer_Name" at 577,-858.49 h60
Bottom Overlay:
  text ".Layer_Name" at 577,-858.49 h60
Top Paste:
  text ".Layer_Name" at 577,-858.49 h60
Bottom Paste:
  text ".Layer_Name" at 577,-858.49 h60
Top Solder:
  text ".Layer_Name" at 577,-858.49 h60
  text ".Layer_Name" at 577,-858.49 h60
Bottom Solder:
  text ".Layer_Name" at 577,-858.49 h60
Drill Guide:
  text ".Layer_Name" at 577,-858.49 h60
M1 Board Outline:
  lines w10: 0,0 0,2296.21 2508.93,2296.21 2508.93,0 0,0
  text ".Layer_Name" at 577,-858.49 h60
M2 Board Dimensions:
  rectangle: 0,-275 125,-150
  rectangle: 125,-400 500,-275
  lines w7: 0,-275 1000,-275 ; 125,-400 125,-150 ; 250,-400 250,-150 ; 500,-400 500,-150 ; 750,-400 750,-150 ; 0,-400 1000,-400 1000,-150 0,-150 0,-400
  text ".Layer_Name" at 577,-858.49 h60
M3 3D STEP Top:
  text ".Layer_Name" at 577,-858.49 h60
M4 3D STEP Bottom:
  text ".Layer_Name" at 577,-858.49 h60
M5 Assembly Top:
  lines w10: -292,-930.17 6308,-930.17 ; -292,-726.83 6310,-726.83 ; -292,-523.5 -292,-1133.5 3713,-1133.5 6310,-1133.5 6310,-523.5 -291.5,-523.5 -291.5,-1133.5 1284,-1133.5 ; 2173,-1133.5 2173,-523.5 ; 3440,-726.83 3440,-523.5 ; 4280,-726.83 4280,-523.5 ; 4902,-1140 4902,-937.17
  text "COMPONENTS MARKED 'DNP' SHOULD NOT BE POPULATED." at 1153.5,-318.5 h60
  text "ASSEMBLY VARIANT:" at 1153,-434 h60
  text ".VariantName" at 2189,-434 h60
  text "PCB VIEWED FROM TOP SIDE" at -228.5,-655.67 h60
  text "BOARD #:" at 2248,-655.67 h60
  text ".PRJ_Number" at 2793.5,-655.67 h60
  text "REV:" at 3638,-655.67 h60
  text ".PCB_Rev" at 3929.5,-655.67 h60
  text "SVN REV:" at 4476,-655.67 h60
  text ".VersionControl_RevNumber" at 4982,-655.67 h60
  text "TID #:" at 2248,-859 h60
  text ".TID" at 2793.5,-859 h60
  text "PLOT NAME =" at -228.5,-1064.34 h60
  text ".plot_File_Name" at 577,-1064.34 h60
  text "GENERATED    :" at 2250,-1064.34 h60
  text ".Print_Date" at 3119.5,-1064.34 h60
  text ".Print_Time" at 3848.5,-1064.34 h60
  text "TEXAS INSTRUMENTS" at 5113,-1064.34 h60
M6 Assembly Bottom:
  lines w10: -292.5,-727.33 6309.5,-727.33 ; -290.5,-930.67 6309.5,-930.67 ; 1115.5,-1140.5 1115.5,-937.67 ; 1737.5,-727.33 1737.5,-524 ; 2577.5,-727.33 2577.5,-524 ; 3844.5,-1134 3844.5,-524 ; 4733.5,-1134 6309,-1134 6309,-524 -292.5,-524 -292.5,-1134 2304.5,-1134 6309.5,-1134 6309.5,-524
  text "COMPONENTS MARKED 'DNP' SHOULD NOT BE POPULATED." at 6102,-318 h60
  text ".VariantName" at 5058,-434 h60
  text "ASSEMBLY VARIANT:" at 6097,-434 h60
  text ".VersionControl_RevNumber" at 1035.5,-656.17 h60
  text "SVN REV:" at 1541.5,-656.17 h60
  text ".PCB_Rev" at 2088,-656.17 h60
  text "REV:" at 2379.5,-656.17 h60
  text ".PRJ_Number" at 3224,-656.17 h60
  text "BOARD #:" at 3769.5,-656.17 h60
  text "PCB VIEWED FROM BOTTOM SIDE" at 6246,-656.17 h60
  text ".TID" at 3224,-859.5 h60
  text "TID #:" at 3769.5,-859.5 h60
  text "TEXAS INSTRUMENTS" at 904.5,-1064.84 h60
  text ".Print_Time" at 2169,-1064.84 h60
  text ".Print_Date" at 2898,-1064.84 h60
  text "GENERATED    :" at 3767.5,-1064.84 h60
  text ".plot_File_Name" at 5440.5,-1064.84 h60
  text "PLOT NAME =" at 6246,-1064.84 h60
M9 Title Sheet:
  drawing of 57 lines, arcs and shapes, not listed
  text "1" at 739.84,8036.5 h70
  text "2" at 3235.5,8036.5 h70
  text "3" at 5724.84,8036.5 h70
  text "4" at 8231.51,8036.5 h70
  text "5" at 10730.5,8036.5 h70
  text "6" at 13235.5,8036.5 h70
  text "A" at -416.5,6893.5 h70
  text "A" at 14383.5,6893.5 h70
  text "B" at -416.5,4513.5 h70
  text "B" at 14383.5,4513.5 h70
  text "C" at -416.5,2138.5 h70
  text "C" at 14383.5,2138.5 h70
  text "PROJECT TITLE:" at 11343.5,277.5 h45
  text ".PRJ_Title" at 11393.5,144.17 h70
  text "DESIGNED FOR:" at 11343.5,-23.5 h45
  text ".PRJ_Customer" at 11393.5,-163.5 h70
  text "D" at -416.5,-231.5 h70
  text "D" at 14383.5,-231.5 h70
  text "FILE NAME:" at 11343.5,-323.5 h45
  text ".PCB_File_Name_No_Path" at 11393.5,-443.5 h70
  text "Texas Instruments (TI) and/or its licensors do not warrant the accuracy or completeness of this specification" at 6374,-605.34 h45
  text "ENGINEER:" at 11343.5,-613.5 h45
  text "LAYOUT BY:" at 12848.5,-613.5 h45
  text "or any information contained therein. TI and/or its licensors do not warrant that this design will meet" at 6329.01,-718 h45
  text ".PRJ_Engineer" at 11393.5,-768.49 h70
  text ".PCB_Layout" at 12899,-768.49 h70
  text "the specifications, will be suitable for your application or fit for any particular purpose, or will operate in" at 6329.01,-830.67 h45
  text ".Layer_Name" at 577,-858.49 h60
  text "ALTIUM DESIGNER VERSION:" at 12848.5,-923.5 h45
  text "an implementation. TI and/or its licensors do not warrant that the design is production worthy. You should" at 6329.01,-943.33 h45
  text "completely validate and test your design implementation to confirm the system functionality for your application." at 6374,-1056 h45
  text ".print_Scale" at 11393.5,-1056.83 h70
  text ".Application_BuildNumber" at 12899,-1056.83 h70
  text "1" at 739.84,-1263.5 h70
  text "2" at 3235.5,-1263.5 h70
  text "3" at 5724.84,-1263.5 h70
  text "4" at 8231.51,-1263.5 h70
  text "5" at 10730.5,-1263.5 h70
  text "6" at 13235.5,-1263.5 h70
M10 Fab Notes:
  drawing of 173 lines, arcs and shapes, not listed
  text "DESIGN INFORMATION" at 12378.02,6201 h60
  text "MIN. TRACK WIDTH:" at 11733.46,6021 h60
  text "8" at 12829.7,6021 h60
  text "MIL" at 12984.46,6021 h60
  text "MIN. CLEARANCE:" at 11733.46,5889 h60
  text "0.2" at 12769.7,5889 h60
  text "mm" at 12984.46,5889 h60
  text "MIN. VIA PAD SIZE:" at 11733.46,5757 h60
  text "24" at 12799.71,5757 h60
  text "MIL" at 12984.46,5757 h60
  text "0.05mm (2MIL)" at 12428.46,5615.29 h60
  text "MINIMUM ANNULAR RING" at 11404.23,5611 h60
  text "EXTERNAL" at 13136.46,5611 h60
  text "PER" at 11604.23,5493 h60
  text "IPC-D-275 CLASS 2 LEVEL C" at 11824.23,5493 h60
  text "MIL, HOLES" at 13312.46,5380.71 h60
  text "+/-" at 12920,5380 h60
  text "+/-" at 13774,5380 h60
  text "REGISTRATION TOLERANCES:" at 11404.23,5375 h60
  text "METAL" at 12604,5375 h60
  text "5" at 13180.2,5375 h60
  text "3" at 14013.2,5375 h60
  text "MIL" at 14129.46,5375 h60
  text "+/-" at 13774,5262 h60
  text "HOLE SIZE TOLERANCE (UNLESS OTHERWISE SPECIFIED):" at 11404.23,5257 h60
  text "3" at 14013.2,5257 h60
  text "MIL" at 14129.46,5257 h60
  text "MATERIAL:" at 11329.46,5047.54 h60
  text "FR-4 High Tg" at 12315.9,4907.21 h60
  text "FR-408" at 11750.46,4898.64 h60
  text "OTHER" at 13238.46,4898.64 h60
  text "X" at 12161,4895 h60
  text "62 MIL (1.6mm) +/-10%" at 12070.56,4735.92 h60
  text "THICKNESS:" at 11404.23,4731.64 h60
  text "X" at 11942.4,4731.64 h60
  text "OTHER" at 13355.46,4731.64 h60
  text "TOLERANCE:" at 11404.23,4573.64 h60
  text "X" at 12243.53,4573.64 h60
  text "ANSI IPC-6012 TYPE 3 CLASS 2" at 12430.48,4573.64 h60
  text "OTHER +/-" at 12430.46,4417.64 h60
  text "BOW & TWIST:" at 11404.23,4260.64 h60
  text "X" at 12243.53,4260.64 h60
  text "ANSI IPC-6012 TYPE 3 CLASS 2" at 12430.48,4260.64 h60
  text "OTHER +/-" at 12430.46,4102.13 h60
  text "DRILLING:" at 11329.46,3963.64 h60
  text "REFERENCE:" at 11404.23,3846.64 h60
  text "X" at 12052.46,3846.64 h60
  text "AS SHOWN" at 12239.46,3846.64 h60
  text "X" at 12953.46,3846.64 h60
  text "NC_DRILL FILES" at 13090.46,3846.64 h60
  text "PTH COPPER THICKNESS:" at 11404.23,3688.64 h60
  text "X" at 12534.46,3688.64 h60
  text "20-30 um" at 12671.46,3688.64 h60
  text "OTHER" at 13388.46,3688.64 h60
  text "BOARD FINISH:" at 11329.46,3529.64 h60
  text "SILKSCREEN:" at 11484.68,3411.64 h60
  text "X" at 12433.46,3411.64 h60
  text "TOP" at 12559.46,3411.64 h60
  text "X" at 12943.46,3411.64 h60
  text "BOTTOM" at 13070.46,3411.64 h60
  text "SILKSCREEN COLOR:" at 11484.68,3244.64 h60
  text "X" at 12432.42,3244.64 h60
  text "WHITE" at 12559.46,3244.64 h60
  text "OTHER" at 13070.46,3244.64 h60
  text "X" at 12563.42,3085.44 h60
  text "GREEN" at 12690.46,3085.44 h60
  text "OTHER" at 13308.46,3085.44 h60
  text "SOLDER RESIST COLOR:" at 11484.68,3074.64 h60
  text "X" at 12563.42,2915.44 h60
  text "MATTE" at 12690.46,2915.44 h60
  text "SEMI-GLOSS" at 13308,2914.8 h60
  text "IMMERSION GOLD (ENIG)" at 12390.46,2726.92 h60
  text "ENEPIG" at 13728,2723.64 h60
  text "SURFACE FINISH:" at 11329.46,2722.64 h60
  text "X" at 12203.51,2722.64 h60
  text "IMM. TIN/SILVER OR EQUIV" at 11659,2565.64 h60
  text "OTHER" at 13090.46,2565.64 h60
  text "ARRAY/PANEL:" at 11329.46,2386.64 h60
  text "CUT AND TRIM PER M1 BOARD OUTLINE" at 12390.46,2382.35 h60
  text "N.C. ROUTE" at 12390.46,2230.64 h60
  text "X" at 13069.46,2230.64 h60
  text "V. SCORE" at 13256.46,2230.64 h60
  text "CERTIFICATION:" at 11329.46,2093.64 h60
  text "MATERIALS AND WORKMANSHIP FOR ALL PCBS" at 12054.46,2093.64 h60
  text "TO MEET OR EXCEED THE REQUIREMENTS OF:" at 12054.46,1995.64 h60
  text "X" at 11680.96,1859.13 h60
  text "ANSI IPC-A-600F CLASS ->" at 11819.96,1859.13 h60
  text "X" at 13459.02,1859.13 h60
  text "2" at 13577.96,1859.14 h60
  text "1" at 13262.96,1857.64 h60
  text "3" at 13931.96,1857.64 h60
  text "X" at 12495.02,1699.64 h60
  text "RoHS" at 12631.96,1699.64 h60
  text "OTHER" at 13276.36,1699.64 h60
  text "PER ORDER" at 13673.42,1699.64 h60
  text "ALL BOARDS MUST MEET OR EXCEED UL94-V0 REQUIREMENTS." at 11357,1534 h60
  text "PCB MUST BEAR THE UL94V-0 UL REGISTERED MATERIAL ID NUMBER" at 11357,1414 h60
  text "ADDITIONAL REQUIREMENTS:" at 11329.46,1240.64 h60
  text "MICROSECTION:" at 11404.23,1125.64 h60
  text "YES" at 12309.96,1125.64 h60
  text "REQUIRED" at 13171.46,969.49 h60
  text "BARE BOARD ELEC. TEST:" at 11404.23,966.64 h60
  text "NONE" at 12709.96,966.64 h60
  text "X" at 13044.46,966.64 h60
  text "PER ORDER" at 13763.46,966.64 h60
  text ".Layer_Name" at 577,-858.49 h60
M11 Gerber Information:
  lines w10: -292,-930.17 6308,-930.17 ; -292,-726.83 6310,-726.83 ; -292,-523.5 -292,-1133.5 3713,-1133.5 6310,-1133.5 6310,-523.5 -291.5,-523.5 -291.5,-1133.5 1284,-1133.5 ; 2173,-1133.5 2173,-523.5 ; 3440,-726.83 3440,-523.5 ; 4280,-726.83 4280,-523.5 ; 4902,-1140 4902,-937.17
  text "ALL ARTWORK VIEWED FROM TOP SIDE" at -228.5,-655.67 h60
  text "BOARD #:" at 2248,-655.67 h60
  text ".PRJ_Number" at 2793.5,-655.67 h60
  text "REV:" at 3638,-655.67 h60
  text ".PCB_Rev" at 3929.5,-655.67 h60
  text "SVN REV:" at 4476,-655.67 h60
  text ".VersionControl_RevNumber" at 4982,-655.67 h60
  text "LAYER NAME =" at -228.5,-858.49 h60
  text "TID #:" at 2248,-859 h60
  text ".TID" at 2793.5,-859 h60
  text "PLOT NAME =" at -228.5,-1064.34 h60
  text ".plot_File_Name" at 577,-1064.34 h60
  text "GENERATED    :" at 2250,-1064.34 h60
  text ".Print_Date" at 3119.5,-1064.34 h60
  text ".Print_Time" at 3848.5,-1064.34 h60
  text "TEXAS INSTRUMENTS" at 5113,-1064.34 h60
M12 Stackup:
  drawing of 191 lines, arcs and shapes, not listed
  text "Layer" at 9790.34,7830 h60
  text "Name" at 10200.26,7830 h60
  text "Material" at 11130,7830 h60
  text "Thickness" at 11989.77,7830 h60
  text "Constant" at 12639.6,7830 h60
  text "Board Layer Stack" at 13209.46,7830 h60
  text "1" at 9790.34,7710 h60
  text "Top Overlay" at 10200.26,7710 h60
  text "2" at 9790.34,7590 h60
  text "Top Solder" at 10200.26,7590 h60
  text "Solder Resist" at 11130,7590 h60
  text "0.40mil" at 11989.77,7590 h60
  text "3.5" at 12639.6,7590 h60
  text "3" at 9790.34,7470 h60
  text "Top Layer" at 10200.26,7470 h60
  text "Copper" at 11130,7470 h60
  text "1.40mil" at 11989.77,7470 h60
  text "4" at 9790.34,7350 h60
  text "Dielectric1" at 10200.26,7350 h60
  text "FR-4" at 11130,7350 h60
  text "59.20mil" at 11989.77,7350 h60
  text "4.8" at 12639.6,7350 h60
  text "5" at 9790.34,7230 h60
  text "Bottom Layer" at 10200.26,7230 h60
  text "Copper" at 11130,7230 h60
  text "1.40mil" at 11989.77,7230 h60
  text "6" at 9790.34,7110 h60
  text "Bottom Solder" at 10200.26,7110 h60
  text "Solder Resist" at 11130,7110 h60
  text "0.40mil" at 11989.77,7110 h60
  text "3.5" at 12639.6,7110 h60
  text "7" at 9790.34,6990 h60
  text "Bottom Overlay" at 10200.26,6990 h60
  text ".Layer_Name" at 577,-858.49 h60
M13 Component Bodies Top:
  text ".Layer_Name" at 577,-858.49 h60
M14 Component Bodies Bottom:
  text ".Layer_Name" at 577,-858.49 h60
M15 Courtyards Top:
  text ".Layer_Name" at 577,-858.49 h60
M16 Courtyards Bottom:
  text ".Layer_Name" at 577,-858.49 h60
Drill Drawing:
  circle w10: c5348.8,3004.69 r22.1
  lines w10: 5326.69,2894.19 5337.74,2894.19 5348.8,2883.14 5359.85,2894.19 5370.9,2894.19 5359.85,2905.23 5370.9,2916.28 5359.85,2916.28 5348.8,2927.34 5337.74,2916.28 5326.69,2916.28 5337.74,2905.23 5326.69,2894.19 ; 5326.69,3082.03 5370.9,3082.03 5370.9,3126.23 5326.69,3126.23 5326.69,3082.03 ; 5326.69,3192.53 5337.74,3192.53 5337.74,3181.48 5359.85,3181.48 5359.85,3192.53 5370.9,3192.53 5370.9,3214.64 5359.85,3214.64 5359.85,3225.69 5337.74,3225.69 5337.74,3214.64 5326.69,3214.64 5326.69,3192.53 ; 5326.69,3325.14 5370.9,3325.14 5348.8,3280.94 5326.69,3325.14
  lines w12: 5286,2853.3 8398.72,2853.3 ; 5286,3350.55 8398.72,3350.55 ; 5601.66,2753.85 5601.66,3450 ; 5918.77,2753.85 5918.77,3450 ; 6540.77,2753.85 6540.77,3450 ; 6785.12,2753.85 6785.12,3450 ; 7145.53,2753.85 7145.53,3450 ; 7854.37,2753.85 7854.37,3450 ; 5286,2753.85 8398.72,2753.85 8398.72,3450 5286,3450 5286,2753.85
  text "Symbol" at 5345.67,3380.39 h72
  text "Quantity" at 5631.5,3380.39 h72
  text "Finished Hole Size" at 5948.6,3380.39 h72
  text "Plated" at 6570.6,3380.39 h72
  text "Hole Type" at 6814.95,3380.39 h72
  text "Drill Layer Pair" at 7175.36,3380.39 h72
  text "Hole Tolerance" at 7884.21,3380.39 h72
  text "21" at 5631.5,3280.94 h60
  text "7.87mil (0.200mm)" at 5948.6,3280.94 h60
  text "PTH" at 6570.6,3280.94 h60
  text "Round" at 6814.95,3280.94 h60
  text "Top Layer - Bottom Layer" at 7175.36,3280.94 h60
  text "6" at 5631.5,3181.48 h60
  text "11.81mil (0.300mm)" at 5948.6,3181.48 h60
  text "PTH" at 6570.6,3181.48 h60
  text "Round" at 6814.95,3181.48 h60
  text "Top Layer - Bottom Layer" at 7175.36,3181.48 h60
  text "507" at 5631.5,3082.03 h60
  text "13.78mil (0.350mm)" at 5948.6,3082.03 h60
  text "PTH" at 6570.6,3082.03 h60
  text "Round" at 6814.95,3082.03 h60
  text "Top Layer - Bottom Layer" at 7175.36,3082.03 h60
  text "7" at 5631.5,2982.59 h60
  text "30.00mil (0.762mm)" at 5948.6,2982.59 h60
  text "PTH" at 6570.6,2982.59 h60
  text "Round" at 6814.95,2982.59 h60
  text "Top Layer - Bottom Layer" at 7175.36,2982.59 h60
  text "2" at 5631.5,2883.14 h60
  text "40.00mil (1.016mm)" at 5948.6,2883.14 h60
  text "PTH" at 6570.6,2883.14 h60
  text "Round" at 6814.95,2883.14 h60
  text "Top Layer - Bottom Layer" at 7175.36,2883.14 h60
  text "543 Total" at 5631.5,2783.69 h60
  text ".Layer_Name" at 577,-858.49 h60
M17 Embedded Cavity:
  text ".Layer_Name" at 577,-858.49 h60
M18 Embedded Assembly:
  text ".Layer_Name" at 577,-858.49 h60
M19 Embedded Keepout:
  text ".Layer_Name" at 577,-858.49 h60

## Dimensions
2502.18,2296.58 to 788.42,0.34 on M3 3D STEP Top
0,2296.58 to 2502.18,2296.58 on M3 3D STEP Top
0,-400 to 1000,-400 on M2 Board Dimensions
0,0 to 2502.18,0 on M2 Board Dimensions
0,0 to 0,2296.58 on M2 Board Dimensions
